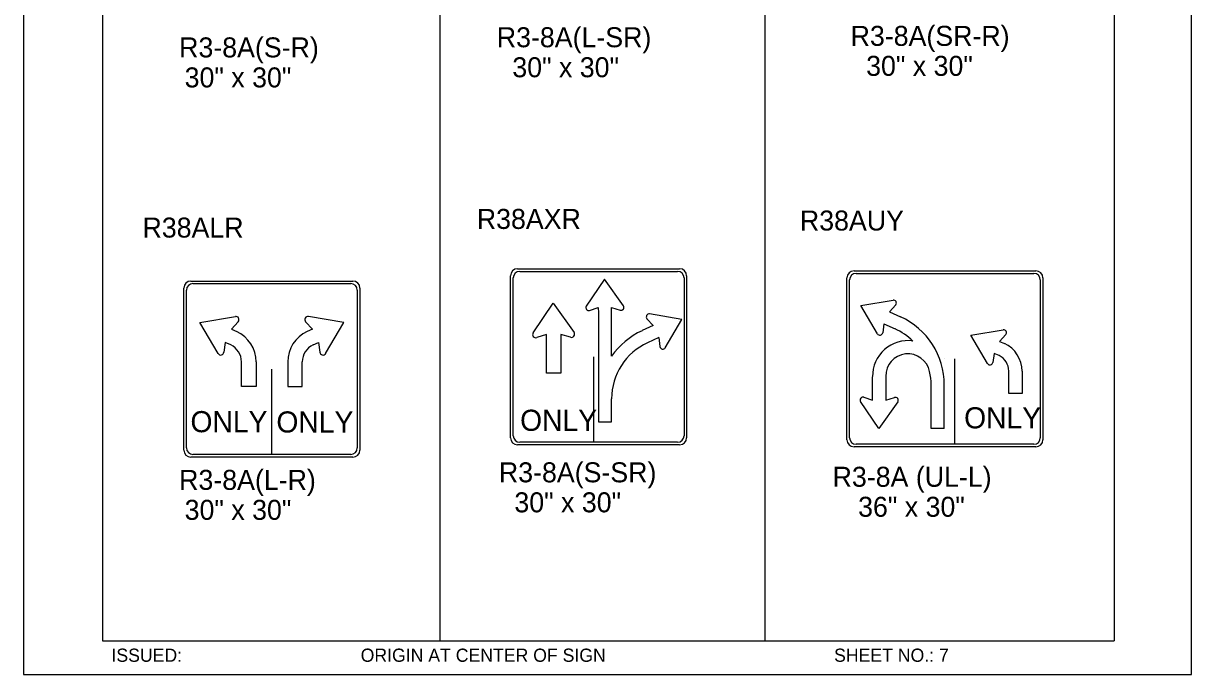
# Model space of a CAD drawing. Extents: x -5299 to 22597, y -19549 to -1808.
# Drawn here: x -5299 to -4598, y -4545 to -4154 of the extents above; entities that cross this region are included whole.
import ezdxf

# ---------------------------------------------------------------- set-up
doc = ezdxf.new("R2010")
doc.units = 0
for name, color, linetype in [('Level 1', 7, 'Continuous'), ('Level 2', 7, 'Continuous'), ('Level 3', 7, 'Continuous'), ('Level 63', 7, 'Continuous')]:
    doc.layers.add(name, color=color, linetype=linetype)

msp = doc.modelspace()

# ---------------------------------------------------------------- linework, layer by layer
at = {"layer": 'Level 1'}
for p, q in [((-5251.55, -3724.36), (-5251.55, -4524.36)), ((-5049.21, -3724.36), (-5049.21, -4524.36)), ((-4854.08, -3724.36), (-4854.08, -4524.36)), ((-4644.53, -3724.36), (-4644.53, -4524.36)), ((-5001.22, -4302.56), (-4906.51, -4302.56)), ((-4799.35, -4303.78), (-4692.71, -4303.78)), ((-5197.28, -4309.91), (-5102.58, -4309.91)), ((-5005.12, -4401.17), (-5005.12, -4306.47)), ((-4950.28, -4307.14), (-4961.26, -4323.44)), ((-4938.89, -4323.2), (-4950.28, -4307.14)), ((-4902.6, -4306.47), (-4902.6, -4401.17)), ((-4803.26, -4402.4), (-4803.26, -4307.69)), ((-4688.8, -4307.69), (-4688.8, -4402.4)), ((-5201.19, -4408.53), (-5201.19, -4313.82)), ((-5098.67, -4313.82), (-5098.67, -4408.53)), ((-4993.17, -4339.49), (-4981.09, -4321.56)), ((-4981.09, -4321.56), (-4968.56, -4339.22)), ((-4959.25, -4326.02), (-4954.03, -4324.32)), ((-4954.03, -4324.32), (-4954.02, -4327.49)), ((-4946.07, -4327.52), (-4946.09, -4324.23)), ((-4946.09, -4324.23), (-4940.85, -4325.82)), ((-4796.49, -4323.11), (-4777.12, -4319.81)), ((-4786.55, -4340.1), (-4796.49, -4323.11)), ((-4775.6, -4322.7), (-4779.3, -4326.76)), ((-5193.14, -4333.23), (-5171.82, -4329.6)), ((-5106.73, -4333.23), (-5128.04, -4329.6)), ((-4953.99, -4327.49), (-4953.99, -4392.79)), ((-4946.07, -4353.51), (-4946.07, -4327.52)), ((-4924.83, -4331.03), (-4921.12, -4335.09)), ((-4903.93, -4331.44), (-4923.3, -4328.14)), ((-4913.87, -4348.43), (-4903.93, -4331.44)), ((-4779.3, -4326.76), (-4772.64, -4329.8)), ((-5182.2, -4351.91), (-5193.14, -4333.23)), ((-5170.15, -4332.78), (-5174.22, -4337.24)), ((-5174.22, -4337.24), (-5171.04, -4338.69)), ((-5129.71, -4332.78), (-5125.64, -4337.24)), ((-5125.64, -4337.24), (-5128.82, -4338.69)), ((-5117.66, -4351.91), (-5106.73, -4333.23)), ((-4921.12, -4335.09), (-4927.79, -4338.13)), ((-4782.65, -4333.96), (-4783.36, -4339.39)), ((-4782.65, -4333.96), (-4775.94, -4337.03)), ((-4730.41, -4340.91), (-4711.03, -4337.61)), ((-5177.91, -4345.16), (-5178.69, -4351.13)), ((-5174.61, -4346.67), (-5177.91, -4345.16)), ((-5125.25, -4346.67), (-5121.96, -4345.16)), ((-5121.96, -4345.16), (-5121.18, -4351.13)), ((-4985.22, -4340.45), (-4990.96, -4342.33)), ((-4985.2, -4343.95), (-4985.22, -4340.45)), ((-4985.17, -4363.57), (-4985.17, -4343.95)), ((-4970.72, -4342.1), (-4976.48, -4340.36)), ((-4976.48, -4340.36), (-4976.46, -4343.98)), ((-4976.46, -4343.98), (-4976.46, -4363.57)), ((-4917.78, -4342.29), (-4924.48, -4345.36)), ((-4917.78, -4342.29), (-4917.07, -4347.72)), ((-4720.47, -4357.9), (-4730.41, -4340.91)), ((-4709.51, -4340.51), (-4713.21, -4344.56)), ((-4713.21, -4344.56), (-4710.32, -4345.88)), ((-4716.56, -4351.77), (-4717.27, -4357.19)), ((-4713.57, -4353.13), (-4716.56, -4351.77)), ((-5168.14, -4371.61), (-5168.14, -4356.82)), ((-5159.44, -4356.88), (-5159.44, -4371.61)), ((-5140.43, -4356.88), (-5140.43, -4371.61)), ((-5131.72, -4371.61), (-5131.72, -4356.82)), ((-4956.82, -4405.08), (-4956.82, -4353.82)), ((-4953.86, -4353.82), (-4953.86, -4353.82)), ((-4746.03, -4355.05), (-4746.03, -4355.05)), ((-4740.06, -4406.31), (-4740.06, -4355.05)), ((-5149.93, -4361.18), (-5149.93, -4361.18)), ((-5149.93, -4412.44), (-5149.93, -4361.18)), ((-4976.46, -4363.57), (-4985.17, -4363.57)), ((-4789.41, -4376.6), (-4789.41, -4365.75)), ((-4781.5, -4365.58), (-4781.5, -4376.57)), ((-4707.69, -4375.8), (-4707.69, -4362.36)), ((-4699.77, -4362.41), (-4699.77, -4375.8)), ((-5159.44, -4371.61), (-5168.14, -4371.61)), ((-5140.43, -4371.61), (-5131.72, -4371.61)), ((-4754.35, -4396.94), (-4754.35, -4370.65)), ((-4746.43, -4396.94), (-4746.43, -4370.65)), ((-4946.07, -4392.79), (-4946.07, -4378.98)), ((-4785.71, -4396.94), (-4796.69, -4380.64)), ((-4794.68, -4378.07), (-4789.46, -4379.77)), ((-4789.46, -4379.77), (-4789.45, -4376.6)), ((-4774.32, -4380.89), (-4785.71, -4396.94)), ((-4781.5, -4376.57), (-4781.52, -4379.86)), ((-4781.52, -4379.86), (-4776.28, -4378.27)), ((-4699.77, -4375.8), (-4707.69, -4375.8)), ((-4953.99, -4392.79), (-4946.07, -4392.79)), ((-4746.44, -4396.94), (-4754.35, -4396.94)), ((-4906.51, -4405.08), (-5001.22, -4405.08)), ((-4692.71, -4406.31), (-4799.35, -4406.31)), ((-5102.58, -4412.44), (-5197.28, -4412.44)), ((-5251.55, -4524.36), (-4644.53, -4524.36))]:
    msp.add_line(p, q, dxfattribs=at)
for centre, radius, start, end in [((-5001.21, -4306.47), 3.91, 90, 180), ((-4906.51, -4306.47), 3.91, 0, 90), ((-4799.35, -4307.7), 3.91, 90, 180), ((-4692.71, -4307.7), 3.91, 0, 90), ((-5197.28, -4313.82), 3.91, 90, 180), ((-5102.58, -4313.82), 3.91, 0, 90), ((-4959.77, -4324.33), 1.75, 148.5743, 287.01476), ((-4940.39, -4324.11), 1.76, 253.93011, 32.50327), ((-4776.93, -4321.53), 1.75, 318.67704, 97.1175), ((-5171.61, -4331.49), 1.93, 318.67704, 97.1175), ((-5128.25, -4331.49), 1.93, 82.8825, 221.32296), ((-4923.5, -4329.86), 1.75, 82.8825, 221.32296), ((-4791.33, -4370.66), 44.9, 0.00076, 65.4104), ((-5179.42, -4356.85), 20, 359.98073, 65.33036), ((-5120.45, -4356.85), 20, 114.66964, 180.01927), ((-4991.53, -4340.47), 1.93, 148.5743, 287.01476), ((-4970.21, -4340.23), 1.93, 253.93011, 32.50327), ((-4909.09, -4378.99), 44.9, 114.5896, 145.43961), ((-4785.1, -4339.11), 1.76, 213.18853, 351.76169), ((-4791.33, -4370.66), 36.98, 45.17736, 65.4104), ((-4710.84, -4339.34), 1.75, 318.67704, 97.1175), ((-4909.09, -4378.99), 36.98, 114.5896, 180), ((-4768.27, -4365.28), 21.15, 81.8031, 181.26004), ((-4717.94, -4362.39), 18.18, 359.98073, 65.33036), ((-5180.6, -4350.83), 1.93, 213.18853, 351.76169), ((-5179.45, -4356.87), 11.28, 0.09236, 64.73623), ((-5120.42, -4356.87), 11.28, 115.26377, 179.90764), ((-5119.26, -4350.83), 1.93, 188.23831, 326.81147), ((-4915.32, -4347.44), 1.76, 188.23831, 326.81147), ((-4768.27, -4365.28), 13.24, 11.14311, 181.26004), ((-4717.96, -4362.41), 10.26, 0.09236, 64.73623), ((-4719.01, -4356.92), 1.76, 213.18853, 351.76169), ((-4791.33, -4370.66), 36.98, 0, 12.40396), ((-4795.2, -4379.76), 1.75, 72.98524, 211.4257), ((-4775.81, -4379.97), 1.76, 327.49673, 106.06989), ((-5001.21, -4401.17), 3.91, 180, 270), ((-4906.51, -4401.17), 3.91, 270, 0), ((-4799.35, -4402.4), 3.91, 180, 270), ((-4692.71, -4402.4), 3.91, 270, 0), ((-5197.28, -4408.53), 3.91, 180, 270), ((-5102.58, -4408.53), 3.91, 270, 0)]:
    msp.add_arc(centre, radius, start, end, dxfattribs=at)
at = {"layer": 'Level 3'}
for p, q in [((-5002.47, -4300.99), (-4905.26, -4300.99)), ((-4800.6, -4302.22), (-4691.46, -4302.22)), ((-5198.54, -4308.35), (-5101.33, -4308.35)), ((-5006.69, -4402.42), (-5006.69, -4305.22)), ((-4901.03, -4305.22), (-4901.03, -4402.42)), ((-4804.83, -4403.65), (-4804.83, -4306.44)), ((-4687.23, -4306.44), (-4687.23, -4403.65)), ((-5202.76, -4409.78), (-5202.76, -4312.57)), ((-5097.1, -4312.57), (-5097.1, -4409.78)), ((-4905.26, -4406.65), (-5002.47, -4406.65)), ((-4691.46, -4407.88), (-4800.6, -4407.88)), ((-5101.33, -4414.01), (-5198.54, -4414.01))]:
    msp.add_line(p, q, dxfattribs=at)
for centre, start, end in [((-5002.47, -4305.22), 90, 180), ((-4905.26, -4305.22), 0, 90), ((-4800.6, -4306.44), 90, 180), ((-4691.46, -4306.44), 0, 90), ((-5198.54, -4312.57), 90, 180), ((-5101.33, -4312.57), 0, 90), ((-5002.47, -4402.42), 180, 270), ((-4905.26, -4402.42), 270, 0), ((-4800.6, -4403.65), 180, 270), ((-4691.46, -4403.65), 270, 0), ((-5198.54, -4409.78), 180, 270), ((-5101.33, -4409.78), 270, 0)]:
    msp.add_arc(centre, 4.23, start, end, dxfattribs=at)
at = {"layer": 'Level 63'}
msp.add_lwpolyline([(-5299.05, -4544.55), (-4598.01, -4544.55), (-4598.01, -3692.17), (-5299.05, -3692.17)], close=True, dxfattribs=at)

# ---------------------------------------------------------------- texts
at = {"layer": 'Level 1'}
for p in [(-5198.77, -4399.09), (-5147.21, -4399.27), (-5000.96, -4398.26), (-4734.53, -4396.77)]:
    msp.add_text('ONLY', height=12.679, dxfattribs=at).set_placement(p)
at = {"layer": 'Level 2'}
for s, p in [('R38AXR', (-5026.95, -4277.09)), ('R38AUY', (-4833.08, -4278.05)), ('R38ALR', (-5227.56, -4282.28))]:
    msp.add_text(s, height=12, dxfattribs=at).set_placement(p)
at = {"layer": 'Level 3'}
for s, height, p in [('R3-8A(L-SR)', 12, (-5014.95, -4168.07)), ('R3-8A(SR-R)', 12, (-4802.64, -4167.24)), ('R3-8A(S-R)', 12, (-5205.58, -4174.17)), ('30" x 30"', 12, (-5005.64, -4186.07)), ('30" x 30"', 12, (-4793.33, -4185.24)), ('30" x 30"', 12, (-5202.27, -4192.17)), ('R3-8A(S-SR)', 12, (-5013.7, -4429.15)), ('R3-8A(L-R)', 12, (-5205.58, -4433.66)), ('R3-8A (UL-L)', 12, (-4813.45, -4431.82)), ('30" x 30"', 12, (-5004.4, -4447.15)), ('30" x 30"', 12, (-5202.27, -4451.66)), ('36" x 30"', 12, (-4798.15, -4449.82)), ('ISSUED:', 7.918, (-5246.18, -4536.85)), ('ORIGIN AT CENTER OF SIGN', 7.9181, (-5096.65, -4536.85)), ('SHEET NO.: 7', 7.918, (-4812.56, -4536.85))]:
    msp.add_text(s, height=height, dxfattribs=at).set_placement(p)

doc.saveas('drawing.dxf')
